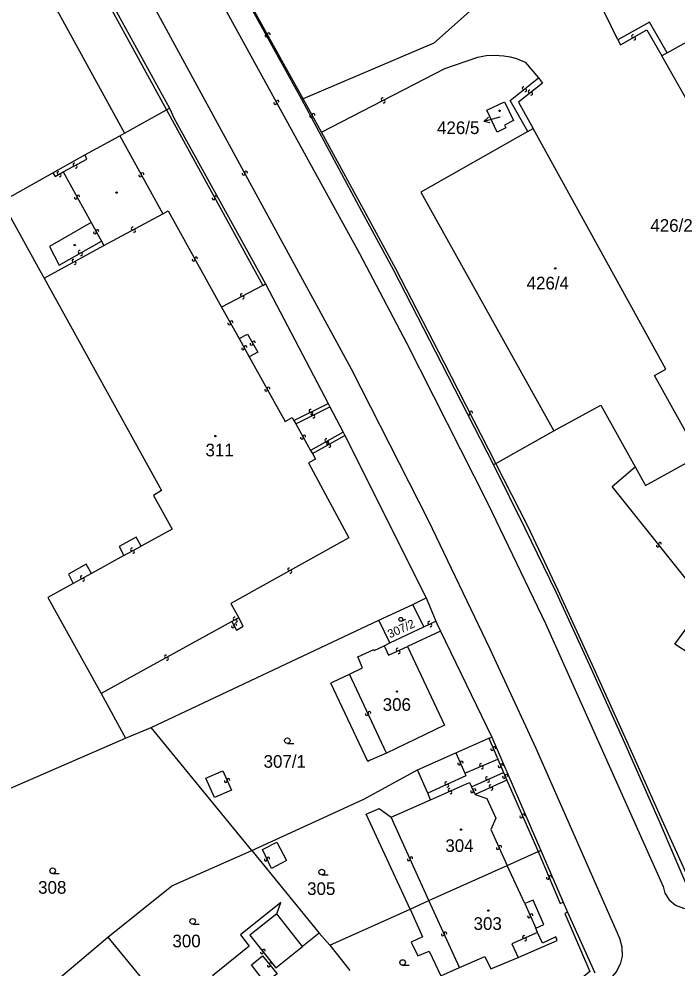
# Model space of a CAD drawing. Extents: x -600391 to -599491, y -1160176 to -1159402.
# Drawn here: x -600056.6 to -599968.2, y -1159960.8 to -1159833.2 of the extents above; entities that cross this region are included whole.
import ezdxf

# ---------------------------------------------------------------- set-up
doc = ezdxf.new("R2010")
doc.units = 0
for name, color, linetype in [('Level 1', 7, 'Continuous'), ('Level 13', 7, 'Continuous'), ('Level 3', 7, 'Continuous'), ('Level 4', 7, 'Continuous'), ('Level 5', 7, 'Continuous'), ('Level 57', 7, 'Continuous')]:
    doc.layers.add(name, color=color, linetype=linetype)

msp = doc.modelspace()

# ---------------------------------------------------------------- linework, layer by layer
at = {"layer": 'Level 1'}
for points in [[(-600091.37, -1159819.77), (-600094.64, -1159813.78), (-600092.5, -1159812.58), (-600093.64, -1159810.41), (-600079.43, -1159802.66), (-600079.57, -1159802.37), (-600076.21, -1159800.53), (-600076.04, -1159800.81), (-600075.4, -1159800.44), (-600074.94, -1159801.26), (-600069.17, -1159797.96), (-600064.75, -1159806.01), (-600064.49, -1159805.85), (-600062.3, -1159809.8), (-600062.62, -1159810), (-600058.11, -1159818.23), (-600058.78, -1159818.63), (-600042.39, -1159848.51)], [(-599976.12, -1159836), (-599981.45, -1159825.03), (-599982.33, -1159823.35), (-599986.7, -1159825.66), (-599993.27, -1159815.55), (-599997.63, -1159818.4), (-599992.01, -1159828.54), (-600000.84, -1159836.43), (-600018.41, -1159843.92)], [(-600018.59, -1159844), (-600027.96, -1159826.96)], [(-600044.75, -1159829.91), (-600036.36, -1159845.18)], [(-599969.46, -1159837.75), (-599955.55, -1159829.92), (-599955.01, -1159830.88)], [(-599969.46, -1159837.75), (-599971.85, -1159833.62), (-599976.12, -1159836)], [(-599969.46, -1159837.75), (-599970.19, -1159838.15)], [(-599946.83, -1159876.34), (-599950.61, -1159869.69), (-599951.91, -1159870.4), (-599970.19, -1159838.15)], [(-600018.41, -1159843.92), (-600018.59, -1159844)], [(-600036.77, -1159845.39), (-600036.36, -1159845.18)], [(-600036.36, -1159845.18), (-600035.72, -1159846.55), (-600023.44, -1159868.75)], [(-599992.81, -1159893.05), (-599999.77, -1159879.53), (-600006.26, -1159866.89), (-600010.52, -1159859.06), (-600018.59, -1159844)], [(-599992.31, -1159848.38), (-599993.71, -1159845.46), (-599991.33, -1159844.32), (-599990.11, -1159846.85), (-599991.34, -1159847.44), (-599991.15, -1159847.83), (-599992.31, -1159848.38)], [(-600042.39, -1159848.51), (-600036.77, -1159845.39)], [(-600047.74, -1159851.46), (-600043.03, -1159848.88)], [(-600043.03, -1159848.88), (-600042.39, -1159848.51)], [(-599988.22, -1159848.31), (-600002.57, -1159856.45), (-599984.72, -1159888.53)], [(-599988.22, -1159848.31), (-599987.48, -1159847.92)], [(-599965.19, -1159891.85), (-599971.16, -1159881.07), (-599969.64, -1159880.25), (-599987.48, -1159847.92)], [(-600052.02, -1159853.85), (-600047.74, -1159851.46)], [(-600058.91, -1159857.7), (-600052.02, -1159853.85)], [(-600058.91, -1159857.7), (-600053.78, -1159866.96), (-600053.18, -1159868.01)], [(-600053.18, -1159868.01), (-600037.41, -1159896.51), (-600038.51, -1159897.19), (-600036.01, -1159901.71), (-600040.17, -1159904)], [(-600023.44, -1159868.75), (-600015.02, -1159884.84)], [(-600015.02, -1159884.84), (-600014.79, -1159885.28)], [(-600014.79, -1159885.28), (-600013.02, -1159888.71)], [(-599984.72, -1159888.53), (-599978.39, -1159885.08), (-599973.76, -1159893.33)], [(-599992.49, -1159892.92), (-599984.72, -1159888.53)], [(-600013.02, -1159888.71), (-600012.79, -1159889.15)], [(-600012.79, -1159889.15), (-600001.85, -1159910.96)], [(-599973.76, -1159893.33), (-599972.37, -1159895.85), (-599965.19, -1159891.85)], [(-599992.81, -1159893.05), (-599992.49, -1159892.92)], [(-599966.31, -1159950.82), (-599970.49, -1159941), (-599975.15, -1159930.49), (-599979.88, -1159920.04), (-599984.4, -1159910.19), (-599988.54, -1159901.64), (-599992.81, -1159893.05)], [(-600040.17, -1159904), (-600040.82, -1159902.78), (-600043.14, -1159904.04), (-600042.48, -1159905.25)], [(-600046.84, -1159907.68), (-600047.54, -1159906.43), (-600049.94, -1159907.76), (-600049.29, -1159909.02)], [(-600042.48, -1159905.25), (-600046.84, -1159907.68)], [(-600049.29, -1159909.02), (-600052.69, -1159910.92), (-600045.53, -1159923.79)], [(-600003.65, -1159911.83), (-600001.85, -1159910.96)], [(-600001.85, -1159910.96), (-600000.58, -1159914.1)], [(-600008.21, -1159913.93), (-600003.65, -1159911.83)], [(-600002.16, -1159914.85), (-600003.65, -1159911.83)], [(-600038.81, -1159928.35), (-600008.21, -1159913.93)], [(-600006.75, -1159917.01), (-600008.21, -1159913.93)], [(-600000.58, -1159914.1), (-600000.44, -1159914.38), (-599999.92, -1159915.41)], [(-600006.75, -1159917.01), (-600002.16, -1159914.85)], [(-599999.92, -1159915.41), (-600004.35, -1159917.49)], [(-599999.92, -1159915.41), (-599993.02, -1159929.64)], [(-600012.15, -1159921.18), (-600010.41, -1159920.33), (-600011.05, -1159918.89), (-600008.91, -1159917.89), (-600008.83, -1159918.04), (-600007.51, -1159917.38)], [(-600007.51, -1159917.38), (-600006.75, -1159917.01)], [(-600004.35, -1159917.49), (-599999.38, -1159928.07), (-600007.19, -1159931.79)], [(-600007.19, -1159931.79), (-600009.49, -1159932.79), (-600009.71, -1159932.93), (-600014.66, -1159922.4), (-600014.35, -1159922.24), (-600012.15, -1159921.18)], [(-600045.53, -1159923.79), (-600042.25, -1159929.81)], [(-600042.25, -1159929.81), (-600038.81, -1159928.35)], [(-600025.31, -1159944.9), (-600038.81, -1159928.35)], [(-600074.33, -1159943.72), (-600042.25, -1159929.81)], [(-599997.87, -1159931.78), (-599993.43, -1159929.81)], [(-599993.43, -1159929.81), (-599993.02, -1159929.64)], [(-599993.02, -1159929.64), (-599986.46, -1159944.88)], [(-600003.02, -1159934.07), (-599997.87, -1159931.78)], [(-600025.31, -1159944.9), (-600010.25, -1159937.99), (-600003.02, -1159934.07)], [(-600001.62, -1159937.18), (-600003.02, -1159934.07)], [(-600006.56, -1159940.43), (-600001.26, -1159938.07)], [(-600001.26, -1159938.07), (-600001.62, -1159937.18)], [(-600004.03, -1159952.75), (-600009.93, -1159940), (-600008.18, -1159939.24), (-600006.56, -1159940.43)], [(-600044.64, -1159956.53), (-600036.04, -1159949.63), (-600025.31, -1159944.9)], [(-600025.31, -1159944.9), (-600016.23, -1159955.97)], [(-599990.96, -1159946.88), (-599986.82, -1159945.01)], [(-599986.82, -1159945.01), (-599986.46, -1159944.88)], [(-599986.46, -1159944.88), (-599983.45, -1159951.83)], [(-600001.5, -1159951.59), (-599990.96, -1159946.88)], [(-599988.6, -1159952.02), (-599990.96, -1159946.88)], [(-600021.92, -1159953.38), (-600021.41, -1159951.86), (-600026.82, -1159956.2), (-600025.67, -1159957.72), (-600030.57, -1159961.73), (-600027.11, -1159966.11), (-600029.4, -1159967.92), (-600029.1, -1159968.3), (-600029.99, -1159969.07), (-600029.39, -1159969.77), (-600028.51, -1159969.14), (-600027.82, -1159968.58)], [(-600004.03, -1159952.75), (-600001.5, -1159951.59)], [(-599987.14, -1159955.3), (-599986.05, -1159954.84), (-599987.48, -1159951.57), (-599988.6, -1159952.02)], [(-599983.45, -1159951.83), (-599982.86, -1159953.19)], [(-600018.49, -1159957.76), (-600021.92, -1159953.38)], [(-600014.83, -1159957.58), (-600004.03, -1159952.75)], [(-600004.03, -1159952.75), (-600002.35, -1159956.46), (-600003.87, -1159957.19), (-600002.97, -1159959.04), (-600001.45, -1159958.4), (-599999.91, -1159961.73), (-599997.4, -1159960.62)], [(-599982.86, -1159953.19), (-599979.19, -1159961.34)], [(-600016.23, -1159955.97), (-600018.49, -1159957.76)], [(-600016.23, -1159955.97), (-600014.83, -1159957.58)], [(-599989.49, -1159959.24), (-599984.26, -1159956.97), (-599984.45, -1159956.47), (-599986.24, -1159957.32), (-599986.91, -1159955.91)], [(-599986.91, -1159955.91), (-599987.14, -1159955.3)], [(-600054.19, -1159964.58), (-600044.64, -1159956.53)], [(-600044.64, -1159956.53), (-600015.94, -1159991.51)], [(-600014.83, -1159957.58), (-600012.1, -1159960.99)], [(-599997.4, -1159960.62), (-599993.96, -1159959.13), (-599993.18, -1159960.76), (-599989.49, -1159959.24)]]:
    msp.add_lwpolyline(points, dxfattribs=at)
at = {"layer": 'Level 13'}
for centre, start, end in [((-600023.33, -1159835.41), 156.3509, 28.4489), ((-600023.01, -1159835.23), 336.1364, 208.7264), ((-599974.08, -1159835.5), 66.9605, 299.0585), ((-599973.9, -1159835.82), 246.746, 119.336), ((-599988.77, -1159842.47), 75.8671, 307.9651), ((-599988.55, -1159842.76), 255.6527, 128.2427), ((-600007.72, -1159843.97), 64.6388, 296.7368), ((-599987.96, -1159842.93), 75.3623, 307.9523), ((-599987.74, -1159843.23), 255.5768, 127.6748), ((-600022.14, -1159844.49), 155.9317, 28.5217), ((-600021.82, -1159844.31), 336.1461, 208.2441), ((-600007.56, -1159844.29), 244.4244, 117.0144), ((-600017.33, -1159846.25), 156.3404, 28.4384), ((-600017.01, -1159846.07), 336.1259, 208.7159), ((-600049.14, -1159852.72), 65.4917, 297.5897), ((-600048.96, -1159853.04), 245.2772, 117.8672), ((-600051.29, -1159853.88), 66.2037, 298.3017), ((-600051.11, -1159854.2), 245.9892, 118.5792), ((-600040.3, -1159854.21), 155.9942, 28.5842), ((-600039.98, -1159854.03), 336.2087, 208.3067), ((-600026.39, -1159854), 155.9389, 28.0369), ((-600026.07, -1159853.82), 335.7245, 208.3145), ((-600048.94, -1159857.21), 156.141, 28.731), ((-600048.62, -1159857.03), 336.3554, 208.4534), ((-600030.44, -1159857.28), 155.9504, 28.5404), ((-600030.12, -1159857.1), 336.1649, 208.2629), ((-600046.37, -1159861.86), 156.1353, 28.7253), ((-600046.05, -1159861.68), 336.3498, 208.4478), ((-600041.31, -1159861.34), 65.7339, 297.8319), ((-600041.13, -1159861.66), 245.5195, 118.1095), ((-600048.43, -1159864.48), 67.1612, 299.2592), ((-600049.27, -1159865.66), 66.0433, 298.1413), ((-600048.25, -1159864.8), 246.9467, 119.5367), ((-600033.11, -1159865.53), 156.2731, 28.8631), ((-600032.79, -1159865.35), 336.4876, 208.5856), ((-600049.09, -1159865.98), 245.8288, 118.4188), ((-600026.65, -1159870.28), 64.7464, 297.3364), ((-600026.49, -1159870.6), 244.9608, 117.0588), ((-600028.33, -1159874.1), 156.2588, 28.8488), ((-600028.01, -1159873.92), 336.4732, 208.5712), ((-600026.15, -1159877.26), 336.507, 208.605), ((-600025.34, -1159876.82), 156.4714, 29.0614), ((-600025.02, -1159876.64), 336.6859, 208.7839), ((-600026.47, -1159877.44), 156.2926, 28.8826), ((-600023.38, -1159883.01), 156.1457, 28.7357), ((-600023.06, -1159882.83), 336.3602, 208.4582), ((-600017.42, -1159885.82), 63.6898, 295.7878), ((-600017.18, -1159886.25), 63.7884, 295.8864), ((-600017.26, -1159886.16), 243.4753, 116.0653), ((-599995.82, -1159886.05), 334.3277, 206.9177), ((-600017.02, -1159886.59), 243.574, 116.164), ((-599996.14, -1159886.21), 154.5421, 26.6401), ((-600018.56, -1159889.45), 156.4704, 29.0604), ((-600018.24, -1159889.27), 336.6849, 208.7829), ((-600015.3, -1159889.77), 66.3352, 298.9252), ((-600015.12, -1159890.09), 246.5496, 118.6476), ((-600015.06, -1159890.21), 66.5054, 298.6034), ((-600014.88, -1159890.53), 246.2909, 118.8809), ((-599970.75, -1159903.92), 166.0594, 38.1574), ((-599970.46, -1159903.7), 345.8449, 218.4349), ((-600041.41, -1159904.46), 65.7917, 297.8897), ((-600041.23, -1159904.78), 245.5772, 118.1672), ((-600020.29, -1159907.13), 66.2772, 298.8672), ((-600020.11, -1159907.45), 246.4917, 118.5897), ((-600048.15, -1159908.19), 65.8342, 298.4242), ((-600047.97, -1159908.51), 246.0487, 118.1467), ((-600027.61, -1159913.73), 66.16, 298.75), ((-600027.43, -1159914.05), 246.3744, 118.4724), ((-600001.45, -1159914.31), 62.7657, 294.8637), ((-600027.83, -1159914.79), 155.9106, 28.5006), ((-600027.51, -1159914.61), 336.1251, 208.2231), ((-600001.29, -1159914.65), 242.5512, 115.1412), ((-600005.71, -1159917.91), 61.9346, 294.0326), ((-600036.85, -1159918.81), 65.9628, 298.5528), ((-600036.67, -1159919.13), 246.1773, 118.2753), ((-600005.55, -1159918.25), 241.7202, 114.3102), ((-600009.84, -1159926.56), 152.428, 24.526), ((-600009.5, -1159926.4), 332.2136, 204.8036), ((-599993, -1159931.27), 150.4312, 23.0212), ((-599992.66, -1159931.13), 330.6456, 202.7436), ((-599997.43, -1159933.21), 151.0623, 23.6523), ((-599997.09, -1159933.07), 331.2768, 203.3748), ((-599994.52, -1159933.39), 60.6961, 292.7941), ((-599991.67, -1159933.43), 330.4183, 202.5163), ((-599994.38, -1159933.73), 240.4816, 113.0716), ((-599992.01, -1159933.57), 150.2039, 22.7939), ((-600028.79, -1159935.56), 151.569, 24.159), ((-600028.45, -1159935.41), 331.7835, 203.8815), ((-599999.15, -1159935.85), 61.6192, 294.2092), ((-599993.69, -1159935.19), 61.2244, 293.3224), ((-599993.55, -1159935.53), 241.0099, 113.5999), ((-599991.41, -1159935), 150.556, 23.146), ((-599991.07, -1159934.86), 330.7705, 202.8685), ((-599999, -1159936.19), 241.8336, 113.9316), ((-599998.73, -1159936.75), 61.2842, 293.3822), ((-599998.59, -1159937.09), 241.0697, 113.6597), ((-599995.69, -1159936.93), 153.2893, 25.8793), ((-599995.35, -1159936.77), 333.5037, 205.6017), ((-599993.22, -1159936.25), 61.5819, 294.1719), ((-599993.07, -1159936.59), 241.7964, 113.8944), ((-599989.09, -1159940.3), 150.8254, 23.4154), ((-599988.75, -1159940.16), 331.0398, 203.1378), ((-599992.24, -1159944.56), 151.9788, 24.5688), ((-599991.9, -1159944.4), 332.1933, 204.2913), ((-600023.42, -1159946.11), 152.6607, 24.7587), ((-600023.08, -1159945.95), 332.4462, 205.0362), ((-600004.2, -1159946.08), 151.7625, 23.8605), ((-600003.86, -1159945.93), 331.5481, 204.1381), ((-599985.51, -1159948.57), 150.1786, 22.7686), ((-599985.17, -1159948.43), 330.393, 202.491), ((-599988.04, -1159953.73), 151.1532, 23.7432), ((-599987.7, -1159953.59), 331.3676, 203.4656), ((-599999.62, -1159956.17), 151.7928, 23.8908), ((-599999.28, -1159956.02), 331.5783, 204.1683), ((-599988.71, -1159956.49), 60.4567, 293.0467), ((-599988.57, -1159956.83), 240.6712, 112.7692), ((-600023.96, -1159958.57), 165.7386, 38.3286), ((-600023.67, -1159958.35), 345.9531, 218.0511), ((-600022.73, -1159960.12), 346.2061, 218.3041), ((-600023.01, -1159960.34), 165.9916, 38.5816)]:
    msp.add_arc(centre, 0.184, start, end, dxfattribs=at)
at = {"layer": 'Level 3'}
for points in [[(-600149.28, -1159836.42), (-600066.99, -1159790.34), (-600036.77, -1159845.39)], [(-600033.38, -1159823.63), (-600033.12, -1159824.1), (-600010.83, -1159864.69), (-600004.5, -1159876.7), (-599993.64, -1159898.18), (-599985.83, -1159914.4), (-599969.99, -1159949.74), (-599969.77, -1159950.61), (-599969.2, -1159951.5), (-599968.36, -1159952.21), (-599967.29, -1159952.61), (-599966.47, -1159952.67), (-599965.66, -1159952.53), (-599965.6, -1159952.51)], [(-600018.41, -1159843.92), (-600027.93, -1159826.73)], [(-599978.39, -1159963.2), (-599977.09, -1159962.14), (-599976.27, -1159961.19), (-599975.7, -1159959.98), (-599975.49, -1159959.08), (-599975.52, -1159957.88), (-599975.83, -1159956.72), (-599987.06, -1159931.18), (-599993.24, -1159917.86), (-600001.54, -1159900.55), (-600011.9, -1159880.23), (-600040.56, -1159827.59)], [(-599976.12, -1159836), (-599975.76, -1159836.66), (-599972.22, -1159834.65), (-599970.19, -1159838.15)], [(-600015.93, -1159848.4), (-599999.36, -1159839.86), (-599994.9, -1159838.32), (-599993.81, -1159838.1), (-599992.68, -1159838.04), (-599991.44, -1159838.12), (-599990.58, -1159838.27), (-599989.7, -1159838.51), (-599988.55, -1159838.98), (-599986.75, -1159841.11)], [(-599988.22, -1159848.31), (-599990.56, -1159844.14), (-599986.75, -1159841.11)], [(-599986.75, -1159841.11), (-599986.23, -1159841.8), (-599989.47, -1159844.35), (-599987.48, -1159847.92)], [(-600015.93, -1159848.4), (-600018.41, -1159843.92)], [(-600036.77, -1159845.39), (-600023.8, -1159868.99)], [(-600043.03, -1159848.88), (-600037.26, -1159859.36)], [(-599992.49, -1159892.92), (-599999.46, -1159879.34), (-600005.94, -1159866.75), (-600010.24, -1159858.83), (-600015.93, -1159848.4)], [(-600050.65, -1159853.74), (-600047.45, -1159852.03), (-600047.74, -1159851.46)], [(-600052.02, -1159853.85), (-600051.74, -1159854.34), (-600050.65, -1159853.74)], [(-600050.65, -1159853.74), (-600046.9, -1159860.51)], [(-600037.26, -1159859.36), (-600036.54, -1159858.98), (-600029.35, -1159871.89)], [(-600046.9, -1159860.51), (-600052.47, -1159863.77), (-600051.17, -1159866.26), (-600045.51, -1159863.02)], [(-600046.9, -1159860.51), (-600045.51, -1159863.02)], [(-600045.17, -1159863.63), (-600037.26, -1159859.36)], [(-600045.51, -1159863.02), (-600045.17, -1159863.63)], [(-600053.18, -1159868.01), (-600045.17, -1159863.63)], [(-600023.8, -1159868.99), (-600029.35, -1159871.89)], [(-600023.8, -1159868.99), (-600023.44, -1159868.75)], [(-600029.35, -1159871.89), (-600026.99, -1159876.13)], [(-600026.99, -1159876.13), (-600025.86, -1159875.51), (-600024.49, -1159877.95), (-600025.63, -1159878.57)], [(-600026.99, -1159876.13), (-600025.63, -1159878.57)], [(-600025.63, -1159878.57), (-600020.81, -1159887.27), (-600019.87, -1159886.73), (-600019.65, -1159887.13)], [(-600019.65, -1159887.13), (-600015.02, -1159884.84)], [(-600019.4, -1159887.57), (-600014.79, -1159885.28)], [(-600019.65, -1159887.13), (-600019.4, -1159887.57)], [(-600019.4, -1159887.57), (-600017.39, -1159891.15)], [(-600013.02, -1159888.71), (-600017.39, -1159891.15)], [(-600017.15, -1159891.58), (-600012.79, -1159889.15)], [(-600017.39, -1159891.15), (-600017.15, -1159891.58)], [(-600017.15, -1159891.58), (-600016.75, -1159892.3), (-600017.69, -1159892.83), (-600012.26, -1159902.87), (-600028.13, -1159911.71), (-600027.06, -1159913.63)], [(-599936.08, -1159910.12), (-599928.46, -1159919.31), (-599966.02, -1159949.92), (-599970.15, -1159940.79), (-599974.83, -1159930.3), (-599979.55, -1159919.91), (-599984.14, -1159909.96), (-599988.22, -1159901.32), (-599992.49, -1159892.92)], [(-599965.34, -1159919.17), (-599968.46, -1159917.16), (-599964.35, -1159911.61), (-599976.85, -1159896), (-599973.76, -1159893.33)], [(-600042.48, -1159905.25), (-600040.17, -1159904)], [(-600046.84, -1159907.68), (-600049.29, -1159909.02)], [(-600027.98, -1159914.14), (-600045.53, -1159923.79)], [(-600027.06, -1159913.63), (-600027.98, -1159914.14)], [(-600027.98, -1159914.14), (-600027.36, -1159915.27), (-600026.44, -1159914.76), (-600027.06, -1159913.63)], [(-600002.16, -1159914.85), (-600000.58, -1159914.1)], [(-600007.51, -1159917.38), (-600007.37, -1159917.67), (-600006.91, -1159918.66), (-600004.35, -1159917.49)], [(-600007.19, -1159931.79), (-600012.15, -1159921.18)], [(-599993.43, -1159929.81), (-599992.23, -1159932.6)], [(-599997.87, -1159931.78), (-599996.66, -1159934.51)], [(-599996.66, -1159934.51), (-599992.23, -1159932.6)], [(-599992.23, -1159932.6), (-599991.46, -1159934.41)], [(-600030.3, -1159937.75), (-600031.46, -1159935.16), (-600029.21, -1159934.18), (-600028.03, -1159936.78), (-600030.3, -1159937.75)], [(-599996.66, -1159934.51), (-599996.52, -1159934.86), (-600001.62, -1159937.18)], [(-599995.78, -1159936.32), (-599991.46, -1159934.41)], [(-599991.46, -1159934.41), (-599991.01, -1159935.45)], [(-600001.26, -1159938.07), (-599996.05, -1159935.76), (-599995.78, -1159936.32)], [(-599991.01, -1159935.45), (-599995.26, -1159937.38)], [(-599991.01, -1159935.45), (-599986.82, -1159945.01)], [(-599995.78, -1159936.32), (-599995.26, -1159937.38)], [(-599995.26, -1159937.38), (-599993.7, -1159937.88), (-599992.52, -1159940.52), (-599993.18, -1159942.08), (-599990.96, -1159946.88)], [(-600001.5, -1159951.59), (-600006.56, -1159940.43)], [(-600020.65, -1159946.25), (-600022.65, -1159947.3), (-600023.85, -1159944.76), (-600021.93, -1159943.78), (-600020.65, -1159946.25)], [(-599986.82, -1159945.01), (-599983.85, -1159952), (-599983.45, -1159951.83)], [(-599997.4, -1159960.62), (-600001.5, -1159951.59)], [(-599988.6, -1159952.02), (-599987.14, -1159955.3)], [(-600021.92, -1159953.38), (-600025.58, -1159956.26), (-600022.07, -1159960.66), (-600018.49, -1159957.76)], [(-599982.86, -1159953.19), (-599983.21, -1159953.35), (-599979.88, -1159961.12), (-599998.98, -1159976.91)], [(-599986.91, -1159955.91), (-599990.37, -1159957.4), (-599989.49, -1159959.24)], [(-600023.48, -1159962.64), (-600025.35, -1159960.25), (-600023.84, -1159959.03), (-600021.9, -1159961.44), (-600023.48, -1159962.64)]]:
    msp.add_lwpolyline(points, dxfattribs=at)
at = {"layer": 'Level 5'}
for p, q in [((-600005.16, -1159914.07), (-600004.6, -1159913.81)), ((-600020.52, -1159930.51), (-600019.65, -1159930.51)), ((-600052.06, -1159947.99), (-600051.19, -1159947.99)), ((-600015.89, -1159948.16), (-600015.02, -1159948.16)), ((-600033.24, -1159954.77), (-600032.36, -1159954.77)), ((-600005.03, -1159960.31), (-600004.16, -1159960.31))]:
    msp.add_line(p, q, dxfattribs=at)
for centre, radius in [((-599992, -1159845.52), 0.09), ((-599992, -1159845.52), 0.0521), ((-600043.47, -1159856.52), 0.09), ((-600043.47, -1159856.52), 0.0521), ((-600049.1, -1159863.57), 0.09), ((-600049.1, -1159863.57), 0.0521), ((-599984.51, -1159866.69), 0.09), ((-599984.51, -1159866.69), 0.0521), ((-600030.19, -1159889.22), 0.09), ((-600030.19, -1159889.22), 0.0521), ((-600005.27, -1159913.83), 0.262), ((-600005.78, -1159923.53), 0.09), ((-600005.78, -1159923.53), 0.0521), ((-600020.52, -1159930.13), 0.375), ((-599997.18, -1159942.08), 0.09), ((-599997.18, -1159942.08), 0.0521), ((-600052.06, -1159947.61), 0.375), ((-600015.89, -1159947.78), 0.375), ((-599993.49, -1159952.95), 0.09), ((-599993.49, -1159952.95), 0.0521), ((-600033.24, -1159954.39), 0.375), ((-600005.03, -1159959.93), 0.375)]:
    msp.add_circle(centre, radius, dxfattribs=at)
at = {"layer": 'Level 57'}
msp.add_line((-599991.94, -1159846.38), (-599994.13, -1159846.95), dxfattribs=at)
msp.add_lwpolyline([(-599993.31, -1159847.12), (-599994.13, -1159846.95), (-599993.49, -1159846.4)], dxfattribs=at)

# ---------------------------------------------------------------- texts
at = {"layer": 'Level 4'}
for s, height, p in [('426/5', 0.1, (-599991.94, -1159846.38)), ('426/2', 1.7, (-599971.73, -1159861.78)), ('426/4', 1.7, (-599988.36, -1159869.52)), ('311', 1.7, (-600031.52, -1159891.94)), ('306', 1.7, (-600007.7, -1159926.13)), ('307/1', 1.7, (-600023.71, -1159933.77)), ('304', 1.7, (-599999.28, -1159945.08)), ('308', 1.7, (-600054.01, -1159950.69)), ('305', 1.7, (-600017.86, -1159950.86)), ('303', 1.7, (-599995.49, -1159955.55)), ('300', 1.7, (-600035.96, -1159957.89))]:
    msp.add_text(s, height=height, dxfattribs=at).set_placement(p)
msp.add_text('307/2', height=1.14, rotation=24.3, dxfattribs=at).set_placement((-600006.74, -1159916.4))
at = {"layer": 'Level 57'}
msp.add_text('426/5', height=1.7, dxfattribs=at).set_placement((-600000.4, -1159848.65))

doc.saveas('drawing.dxf')
